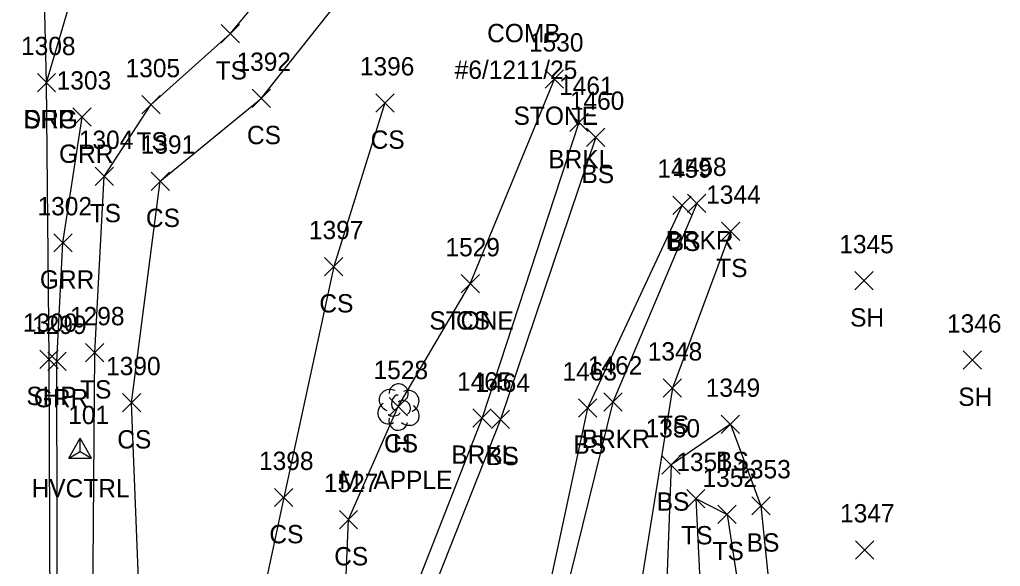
# Model space of a CAD drawing. Extents: x 1618262 to 1622220, y 273782 to 283685.
# Drawn here: x 1622080.2 to 1622187.3, y 282758.7 to 282818.4 of the extents above; entities that cross this region are included whole.
import ezdxf

# ---------------------------------------------------------------- set-up
doc = ezdxf.new("R2010")
doc.units = 0
for name, color, linetype in [('C_A', 7, 'Continuous'), ('C_I', 7, 'Continuous'), ('CPSM', 7, 'Continuous'), ('L_A', 7, 'Continuous'), ('L_C', 7, 'Continuous'), ('L_I', 7, 'Continuous'), ('L_TIC', 7, 'Continuous'), ('LASF', 7, 'Continuous'), ('LAWE', 7, 'Continuous'), ('LELB', 7, 'Continuous'), ('LTD', 7, 'Continuous'), ('P_A', 7, 'Continuous'), ('P_I', 7, 'Continuous'), ('P_TIC', 7, 'Continuous'), ('PSP', 7, 'Continuous'), ('R_A', 7, 'Continuous'), ('R_I', 7, 'Continuous'), ('R_TIC', 7, 'Continuous'), ('RDG', 7, 'Continuous'), ('RGR', 7, 'Continuous'), ('U_A', 7, 'Continuous'), ('U_C', 7, 'Continuous')]:
    doc.layers.add(name, color=color, linetype=linetype)

msp = doc.modelspace()

# ---------------------------------------------------------------- linework, layer by layer
at = {"layer": 'CPSM'}
for p, q in [((1622085.6, 282770.55), (1622086.85, 282772.72)), ((1622088.1, 282770.55), (1622086.85, 282772.72)), ((1622086.85, 282771.27), (1622086.85, 282772.72)), ((1622085.6, 282770.55), (1622086.85, 282771.27)), ((1622086.85, 282771.27), (1622086.85, 282771.27)), ((1622086.85, 282771.27), (1622088.1, 282770.55)), ((1622085.6, 282770.55), (1622088.1, 282770.55))]:
    msp.add_line(p, q, dxfattribs=at)
at = {"layer": 'L_TIC'}
for points in [[(1622102.23, 282815.89), (1622104.23, 282817.89)], [(1622104.23, 282815.89), (1622102.23, 282817.89)], [(1622137.64, 282810.94), (1622139.64, 282812.94)], [(1622139.64, 282810.94), (1622137.64, 282812.94)], [(1622105.62, 282808.83), (1622107.62, 282810.83)], [(1622107.62, 282808.83), (1622105.62, 282810.83)], [(1622093.58, 282808.14), (1622095.58, 282810.14)], [(1622095.58, 282808.14), (1622093.58, 282810.14)], [(1622119.13, 282808.33), (1622121.13, 282810.33)], [(1622121.13, 282808.33), (1622119.13, 282810.33)], [(1622140.32, 282806.2), (1622142.32, 282808.2)], [(1622142.32, 282806.2), (1622140.32, 282808.2)], [(1622142.15, 282804.58), (1622144.15, 282806.58)], [(1622144.15, 282804.58), (1622142.15, 282806.58)], [(1622088.47, 282800.31), (1622090.47, 282802.31)], [(1622090.47, 282800.31), (1622088.47, 282802.31)], [(1622094.59, 282799.79), (1622096.59, 282801.79)], [(1622096.59, 282799.79), (1622094.59, 282801.79)], [(1622151.58, 282797.17), (1622153.58, 282799.17)], [(1622153.58, 282797.17), (1622151.58, 282799.17)], [(1622153.18, 282797.36), (1622155.18, 282799.36)], [(1622155.18, 282797.36), (1622153.18, 282799.36)], [(1622156.9, 282794.32), (1622158.9, 282796.32)], [(1622158.9, 282794.32), (1622156.9, 282796.32)], [(1622113.53, 282790.46), (1622115.53, 282792.46)], [(1622115.53, 282790.46), (1622113.53, 282792.46)], [(1622128.44, 282788.59), (1622130.44, 282790.59)], [(1622130.44, 282788.59), (1622128.44, 282790.59)], [(1622128.44, 282788.59), (1622130.44, 282790.59)], [(1622130.44, 282788.59), (1622128.44, 282790.59)], [(1622171.44, 282788.92), (1622173.44, 282790.92)], [(1622173.44, 282788.92), (1622171.44, 282790.92)], [(1622087.43, 282781.06), (1622089.43, 282783.06)], [(1622089.43, 282781.06), (1622087.43, 282783.06)], [(1622183.26, 282780.26), (1622185.26, 282782.26)], [(1622185.26, 282780.26), (1622183.26, 282782.26)], [(1622150.52, 282777.21), (1622152.52, 282779.21)], [(1622152.52, 282777.21), (1622150.52, 282779.21)], [(1622091.46, 282775.61), (1622093.46, 282777.61)], [(1622093.46, 282775.61), (1622091.46, 282777.61)], [(1622144.03, 282775.68), (1622146.03, 282777.68)], [(1622146.03, 282775.68), (1622144.03, 282777.68)], [(1622120.59, 282775.18), (1622122.59, 282777.18)], [(1622122.59, 282775.18), (1622120.59, 282777.18)], [(1622141.26, 282775.03), (1622143.26, 282777.03)], [(1622143.26, 282775.03), (1622141.26, 282777.03)], [(1622129.74, 282773.94), (1622131.74, 282775.94)], [(1622131.74, 282773.94), (1622129.74, 282775.94)], [(1622131.75, 282773.79), (1622133.75, 282775.79)], [(1622133.75, 282773.79), (1622131.75, 282775.79)], [(1622156.86, 282773.25), (1622158.86, 282775.25)], [(1622158.86, 282773.25), (1622156.86, 282775.25)], [(1622156.86, 282773.25), (1622158.86, 282775.25)], [(1622158.86, 282773.25), (1622156.86, 282775.25)], [(1622150.37, 282768.82), (1622152.37, 282770.82)], [(1622152.37, 282768.82), (1622150.37, 282770.82)], [(1622108.07, 282765.26), (1622110.07, 282767.26)], [(1622110.07, 282765.26), (1622108.07, 282767.26)], [(1622153.08, 282765.14), (1622155.08, 282767.14)], [(1622155.08, 282765.14), (1622153.08, 282767.14)], [(1622153.08, 282765.14), (1622155.08, 282767.14)], [(1622155.08, 282765.14), (1622153.08, 282767.14)], [(1622160.19, 282764.35), (1622162.19, 282766.35)], [(1622162.19, 282764.35), (1622160.19, 282766.35)], [(1622115.15, 282762.85), (1622117.15, 282764.85)], [(1622117.15, 282762.85), (1622115.15, 282764.85)], [(1622156.5, 282763.42), (1622158.5, 282765.42)], [(1622158.5, 282763.42), (1622156.5, 282765.42)], [(1622171.52, 282759.54), (1622173.52, 282761.54)], [(1622173.52, 282759.54), (1622171.52, 282761.54)]]:
    msp.add_lwpolyline(points, dxfattribs=at)
at = {"layer": 'LASF'}
msp.add_lwpolyline([(1622129.44, 282789.59), (1622138.64, 282811.94)], dxfattribs=at)
at = {"layer": 'LAWE'}
for points in [[(1622141.32, 282807.2), (1622130.74, 282774.94), (1622121.61, 282751.65), (1622120.62, 282736.19), (1622116.22, 282716.11), (1622112.29, 282712.25), (1622108.48, 282711.9), (1622107.61, 282715.75)], [(1622154.18, 282798.36), (1622145.03, 282776.68), (1622137.04, 282744.35), (1622134.91, 282727.3), (1622131.15, 282718.74), (1622121.39, 282708.67), (1622112.79, 282701.56), (1622107.39, 282699)]]:
    msp.add_lwpolyline(points, dxfattribs=at)
at = {"layer": 'LELB'}
for points in [[(1622121.16, 282596.52), (1622112.16, 282596.84), (1622102.98, 282598.76), (1622094.2, 282601.85), (1622088.69, 282605.57), (1622085.73, 282618.96), (1622084.9, 282649.7), (1622087.6, 282681.1), (1622086.98, 282710.97), (1622088.16, 282744.85), (1622088.43, 282782.06), (1622089.47, 282801.31), (1622094.58, 282809.14), (1622103.23, 282816.89), (1622109.05, 282823.9), (1622118.48, 282854.45), (1622116.35, 282881.37), (1622111.85, 282914.54), (1622109.18, 282938.55)], [(1622091.19, 282690.57), (1622090.7, 282707.3), (1622092.69, 282721.62), (1622095.2, 282734.09), (1622093.37, 282753.63), (1622092.46, 282776.61), (1622095.59, 282800.79), (1622106.62, 282809.83), (1622119.29, 282825.78), (1622124.75, 282845.14)], [(1622120.13, 282809.33), (1622114.53, 282791.46), (1622109.07, 282766.26), (1622104.77, 282745.95)], [(1622143.15, 282805.58), (1622132.75, 282774.79), (1622123.45, 282751.29), (1622123, 282734.46), (1622117.17, 282715.28), (1622113.09, 282710.69), (1622107.29, 282710.5)], [(1622152.58, 282798.17), (1622142.26, 282776.03), (1622135.44, 282744.3), (1622133.43, 282728.57), (1622130.82, 282719.87), (1622119.84, 282709.84), (1622112.9, 282703.42), (1622107.41, 282701.55), (1622107.45, 282705.27), (1622107.33, 282706.57), (1622107.29, 282710.5), (1622106.87, 282715.56)], [(1622157.9, 282795.32), (1622151.52, 282778.21), (1622146.29, 282745.58), (1622145.16, 282735.98), (1622131.78, 282716.64), (1622123.79, 282704.55), (1622117.42, 282698.44), (1622102.74, 282693.29)], [(1622115.27, 282742.96), (1622116.15, 282763.85), (1622121.59, 282776.18), (1622129.44, 282789.59)], [(1622157.86, 282774.25), (1622151.37, 282769.82), (1622150.47, 282745.52), (1622148.38, 282732.82)], [(1622157.86, 282774.25), (1622161.19, 282765.35), (1622162.64, 282751.17), (1622162.69, 282732.54), (1622148.38, 282732.82)], [(1622154.08, 282766.14), (1622155.07, 282746.11), (1622152.29, 282738.11)], [(1622154.08, 282766.14), (1622157.5, 282764.42), (1622159.98, 282748.3), (1622159.14, 282735.35), (1622152.29, 282738.11)]]:
    msp.add_lwpolyline(points, dxfattribs=at)
at = {"layer": 'LTD'}
msp.add_line((1622121.59, 282776.18), (1622121.59, 282776.18), dxfattribs=at)
msp.add_line((1622121.59, 282776.18), (1622121.59, 282776.18), dxfattribs=at)
msp.add_arc((1622121.63, 282777.62), 1.05, 335.5272, 180.9563, dxfattribs=at)
for centre, major_axis, ratio, start_param, end_param in [((1622120.79, 282776.85), (1.21, -0.51), 0.895232, 1.570796, 4.712389), ((1622122.63, 282776.76), (-1.14, -0.48), 0.949671, 1.570796, 4.712389), ((1622121.38, 282776.64), (-0.208, -0.792), 0.645439, 3.141593, 6.283185), ((1622122.09, 282776.01), (-0.5, 0.667), 0.989748, 3.141593, 6.283185), ((1622120.5, 282775.47), (0.58, -1.04), 0.959034, 3.141593, 6.283185), ((1622121.13, 282775.43), (-0.625, -0.083), 0.423636, 0, 3.141593), ((1622122.59, 282775.35), (-1.09, 0.79), 0.841452, 1.570796, 4.712389), ((1622121.59, 282774.68), (0.26, 1.06), 0.942809, 1.570796, 4.712389)]:
    msp.add_ellipse(centre, major_axis=major_axis, ratio=ratio, start_param=start_param, end_param=end_param, dxfattribs=at)
at = {"layer": 'P_TIC'}
for points in [[(1622082.17, 282810.55), (1622084.17, 282812.55)], [(1622084.17, 282810.55), (1622082.17, 282812.55)], [(1622082.45, 282780.35), (1622084.45, 282782.35)], [(1622084.45, 282780.35), (1622082.45, 282782.35)]]:
    msp.add_lwpolyline(points, dxfattribs=at)
at = {"layer": 'PSP'}
msp.add_lwpolyline([(1622063.9, 282356.42), (1622068.96, 282404.45), (1622072.02, 282437.73), (1622074.67, 282475.61), (1622076.63, 282501.43), (1622078.27, 282531.06), (1622079.38, 282546.3), (1622079.58, 282558.79), (1622081.73, 282610.73), (1622082.59, 282649.97), (1622083.39, 282682.72), (1622083.74, 282709.96), (1622083.62, 282744.12), (1622083.45, 282781.35), (1622083.17, 282811.55), (1622082.7, 282831.31), (1622081.46, 282858.35), (1622080.36, 282881.43), (1622078.26, 282910.95), (1622077.13, 282929.74), (1622076.71, 282935.51)], dxfattribs=at)
at = {"layer": 'R_TIC'}
for points in [[(1622082.17, 282810.55), (1622084.17, 282812.55)], [(1622084.17, 282810.55), (1622082.17, 282812.55)], [(1622086.05, 282806.79), (1622088.05, 282808.79)], [(1622088.05, 282806.79), (1622086.05, 282808.79)], [(1622083.96, 282793.06), (1622085.96, 282795.06)], [(1622085.96, 282793.06), (1622083.96, 282795.06)], [(1622083.3, 282780.11), (1622085.3, 282782.11)], [(1622085.3, 282780.11), (1622083.3, 282782.11)]]:
    msp.add_lwpolyline(points, dxfattribs=at)
at = {"layer": 'RDG'}
msp.add_lwpolyline([(1622083.17, 282811.55), (1622088.98, 282831.33), (1622104.37, 282853.37), (1622106.52, 282882.63), (1622108.61, 282914.04), (1622104.11, 282939.03)], dxfattribs=at)
at = {"layer": 'RGR'}
msp.add_lwpolyline([(1622085.58, 282605.25), (1622083.68, 282611.3), (1622082.78, 282619.4), (1622083.48, 282650.06), (1622084.1, 282682.87), (1622084.66, 282710.12), (1622084.36, 282744.32), (1622084.3, 282781.11), (1622084.96, 282794.06), (1622087.05, 282807.79)], dxfattribs=at)

# ---------------------------------------------------------------- texts
at = {"layer": 'C_A'}
msp.add_text('HVCTRL', height=2, dxfattribs=at).set_placement((1622081.54, 282766.27))
at = {"layer": 'C_I'}
msp.add_text('101', height=2, dxfattribs=at).set_placement((1622085.54, 282774.27))
at = {"layer": 'L_A'}
for s, p in [('TS', (1622101.64, 282811.89)), ('STONE', (1622134.18, 282806.94)), ('CS', (1622105.06, 282804.83)), ('TS', (1622092.99, 282804.14)), ('CS', (1622118.57, 282804.33)), ('BRKL', (1622137.97, 282802.2)), ('BS', (1622141.59, 282800.58)), ('TS', (1622087.88, 282796.31)), ('CS', (1622094.03, 282795.79)), ('BRKR', (1622150.77, 282793.36)), ('BS', (1622151.02, 282793.17)), ('TS', (1622156.31, 282790.32)), ('CS', (1622112.97, 282786.46)), ('STONE', (1622124.98, 282784.59)), ('CS', (1622127.88, 282784.59)), ('SH', (1622170.93, 282784.92)), ('TS', (1622086.84, 282777.06)), ('SH', (1622182.74, 282776.26)), ('TS', (1622149.93, 282773.21)), ('CS', (1622090.9, 282771.61)), ('BRKR', (1622141.62, 282771.68)), ('CS', (1622120.03, 282771.18)), ('H', (1622121.02, 282771.18)), ('BS', (1622140.71, 282771.03)), ('BRKL', (1622127.38, 282769.94)), ('BS', (1622131.19, 282769.79)), ('BS', (1622156.3, 282769.25)), ('BS', (1622156.3, 282769.25)), ('BS', (1622149.81, 282764.82)), ('CS', (1622107.51, 282761.26)), ('TS', (1622152.49, 282761.14)), ('TS', (1622152.49, 282761.14)), ('BS', (1622159.64, 282760.35)), ('CS', (1622114.59, 282758.85)), ('TS', (1622155.91, 282759.42))]:
    msp.add_text(s, height=2, dxfattribs=at).set_placement(p)
at = {"layer": 'L_C'}
msp.add_text('M. APPLE', height=2, dxfattribs=at).set_placement((1622115.16, 282767.18))
at = {"layer": 'L_I'}
for s, p in [('1530', (1622135.86, 282814.94)), ('1305', (1622091.81, 282812.14)), ('1392', (1622103.92, 282812.83)), ('1396', (1622117.39, 282812.33)), ('1461', (1622139.15, 282810.2)), ('1460', (1622140.32, 282808.58)), ('1304', (1622086.7, 282804.31)), ('1391', (1622093.46, 282803.79)), ('1458', (1622151.49, 282801.36)), ('1459', (1622149.88, 282801.17)), ('1344', (1622155.21, 282798.32)), ('1397', (1622111.83, 282794.46)), ('1345', (1622169.75, 282792.92)), ('1529', (1622126.74, 282792.59)), ('1529', (1622126.74, 282792.59)), ('1298', (1622085.74, 282785.06)), ('1346', (1622181.51, 282784.26)), ('1348', (1622148.83, 282781.21)), ('1390', (1622089.68, 282779.61)), ('1528', (1622118.89, 282779.18)), ('1528', (1622118.89, 282779.18)), ('1463', (1622139.52, 282779.03)), ('1462', (1622142.29, 282779.68)), ('1465', (1622128, 282777.94)), ('1464', (1622130.01, 282777.79)), ('1349', (1622155.16, 282777.25)), ('1349', (1622155.16, 282777.25)), ('1350', (1622148.59, 282772.82)), ('1398', (1622106.38, 282769.26)), ('1351', (1622151.95, 282769.14)), ('1351', (1622151.95, 282769.14)), ('1353', (1622158.5, 282768.35)), ('1352', (1622154.81, 282767.42)), ('1527', (1622113.46, 282766.85)), ('1347', (1622169.83, 282763.54))]:
    msp.add_text(s, height=2, dxfattribs=at).set_placement(p)
at = {"layer": 'P_A'}
for p in [(1622080.7, 282806.55), (1622080.98, 282776.35)]:
    msp.add_text('SHP', height=2, dxfattribs=at).set_placement(p)
at = {"layer": 'P_I'}
for s, p in [('1308', (1622080.39, 282814.55)), ('1300', (1622080.59, 282784.35))]:
    msp.add_text(s, height=2, dxfattribs=at).set_placement(p)
at = {"layer": 'R_A'}
for s, p in [('DRG', (1622080.65, 282806.55)), ('GRR', (1622084.54, 282802.79)), ('GRR', (1622082.45, 282789.06)), ('GRR', (1622081.79, 282776.11))]:
    msp.add_text(s, height=2, dxfattribs=at).set_placement(p)
at = {"layer": 'R_I'}
for s, p in [('1308', (1622080.39, 282814.55)), ('1303', (1622084.28, 282810.79)), ('1302', (1622082.19, 282797.06)), ('1299', (1622081.6, 282784.11))]:
    msp.add_text(s, height=2, dxfattribs=at).set_placement(p)
at = {"layer": 'U_A'}
msp.add_text('COMB', height=2, dxfattribs=at).set_placement((1622131.29, 282815.96))
at = {"layer": 'U_C'}
msp.add_text('#6/1211/25', height=2, dxfattribs=at).set_placement((1622127.75, 282811.96))

doc.saveas('drawing.dxf')
